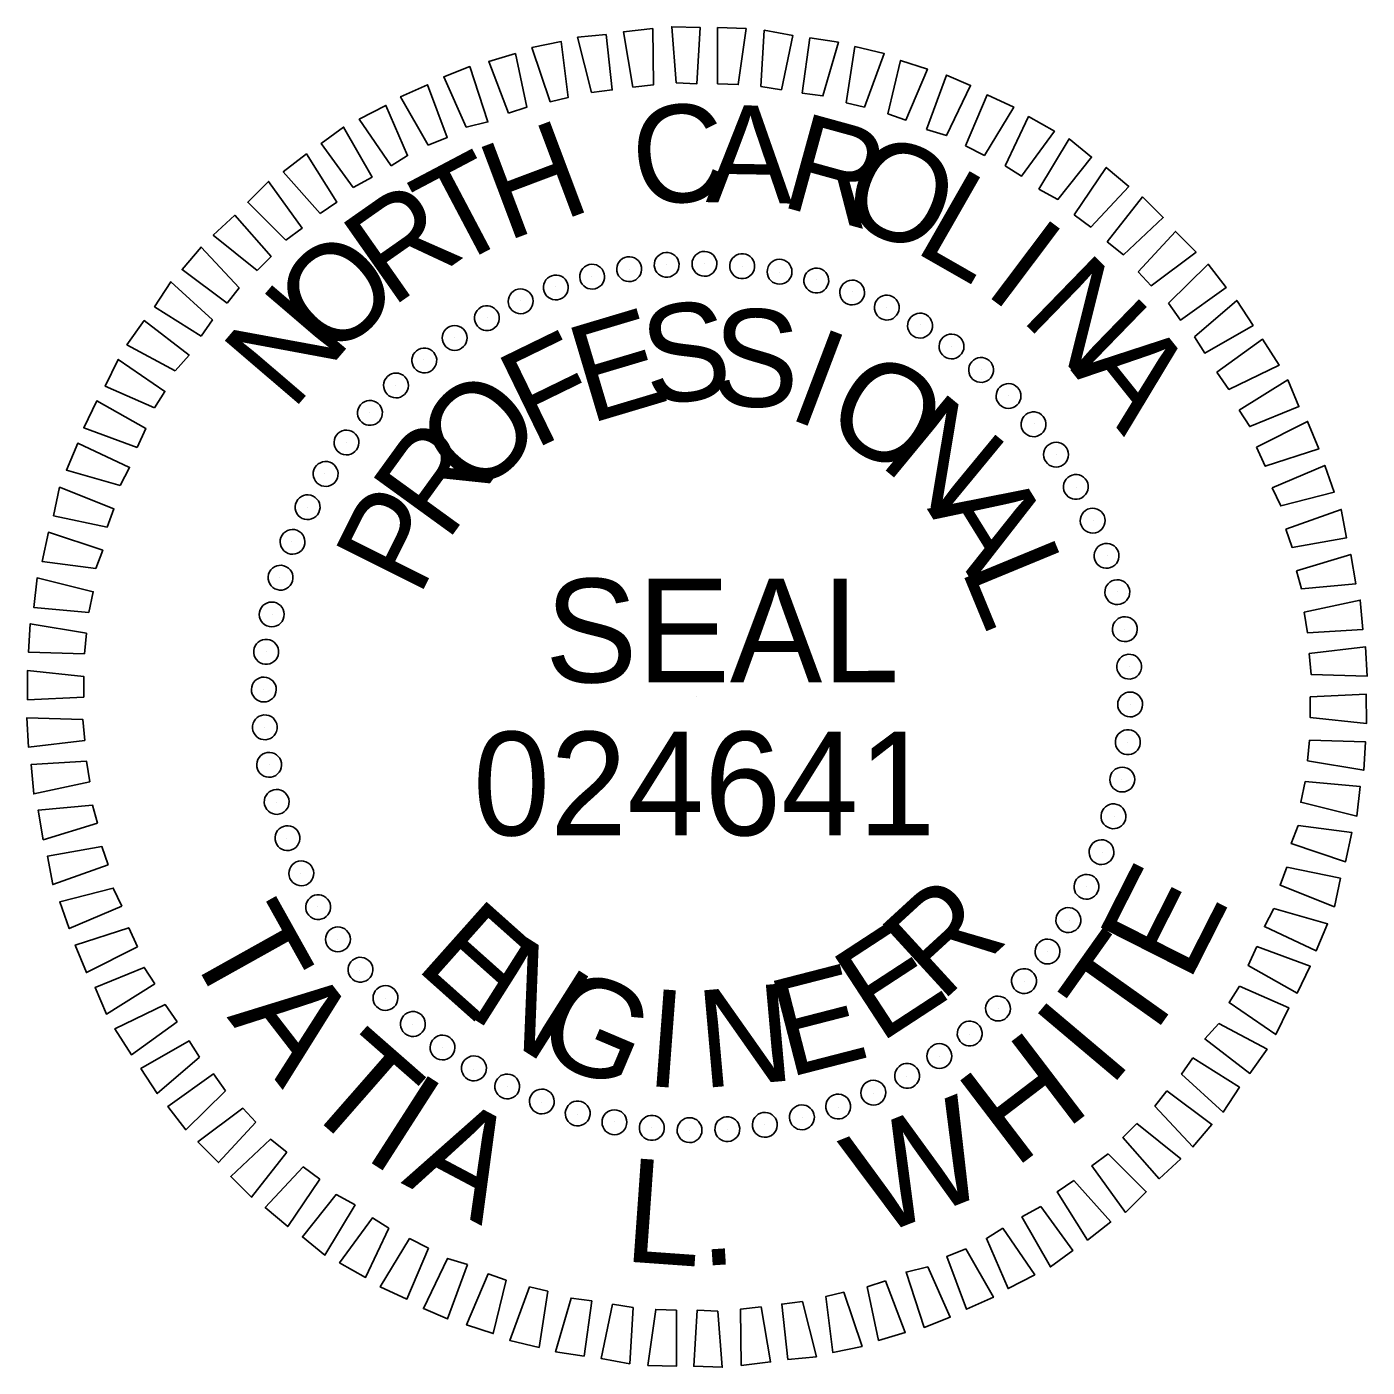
# Model space of a CAD drawing. Extents: x 573468 to 580768, y -57414 to -51768.
# Drawn here: x 580590.4 to 580668, y -54257.1 to -54179.5 of the extents above; entities that cross this region are included whole.
import ezdxf

# ---------------------------------------------------------------- set-up
doc = ezdxf.new("R2010")
doc.units = 0
doc.layers.add('Sheet Professional Seal CELL', color=7, linetype='Continuous')

msp = doc.modelspace()

# ---------------------------------------------------------------- linework, layer by layer
at = {"layer": 'Sheet Professional Seal CELL'}
for p, q in [((580625.308, -54193.527), (580625.308, -54193.527)), ((580627.458, -54193.227), (580627.458, -54193.227)), ((580629.658, -54193.176), (580629.658, -54193.176)), ((580631.858, -54193.325), (580631.858, -54193.325)), ((580634.008, -54193.675), (580634.008, -54193.675)), ((580621.008, -54194.528), (580621.008, -54194.528)), ((580623.108, -54193.928), (580623.108, -54193.928)), ((580636.108, -54194.124), (580636.108, -54194.124)), ((580619.008, -54195.329), (580619.008, -54195.329)), ((580638.208, -54194.824), (580638.208, -54194.824)), ((580640.208, -54195.723), (580640.208, -54195.723)), ((580617.059, -54196.329), (580617.059, -54196.329)), ((580642.159, -54196.723), (580642.159, -54196.723)), ((580615.159, -54197.48), (580615.159, -54197.48)), ((580643.959, -54197.972), (580643.959, -54197.972)), ((580613.409, -54198.73), (580613.409, -54198.73)), ((580645.709, -54199.322), (580645.709, -54199.322)), ((580611.76, -54200.23), (580611.76, -54200.23)), ((580647.26, -54200.822), (580647.26, -54200.822)), ((580610.26, -54201.781), (580610.26, -54201.781)), ((580648.76, -54202.471), (580648.76, -54202.471)), ((580608.91, -54203.531), (580608.91, -54203.531)), ((580650.011, -54204.221), (580650.011, -54204.221)), ((580607.661, -54205.331), (580607.661, -54205.331)), ((580651.161, -54206.121), (580651.161, -54206.121)), ((580606.661, -54207.282), (580606.661, -54207.282)), ((580652.162, -54208.07), (580652.162, -54208.07)), ((580605.762, -54209.282), (580605.762, -54209.282)), ((580652.962, -54210.07), (580652.962, -54210.07)), ((580605.062, -54211.382), (580605.062, -54211.382)), ((580653.563, -54212.17), (580653.563, -54212.17)), ((580604.613, -54213.482), (580604.613, -54213.482)), ((580653.963, -54214.37), (580653.963, -54214.37)), ((580604.263, -54215.632), (580604.263, -54215.632)), ((580654.264, -54216.52), (580654.264, -54216.52)), ((580604.114, -54217.832), (580604.114, -54217.832)), ((580629.214, -54218.276), (580629.214, -54218.276)), ((580654.314, -54218.72), (580654.314, -54218.72)), ((580604.165, -54220.032), (580604.165, -54220.032)), ((580654.165, -54220.92), (580654.165, -54220.92)), ((580604.465, -54222.182), (580604.465, -54222.182)), ((580653.815, -54223.07), (580653.815, -54223.07)), ((580604.866, -54224.382), (580604.866, -54224.382)), ((580653.366, -54225.17), (580653.366, -54225.17)), ((580605.466, -54226.482), (580605.466, -54226.482)), ((580652.666, -54227.27), (580652.666, -54227.27)), ((580606.267, -54228.482), (580606.267, -54228.482)), ((580651.767, -54229.27), (580651.767, -54229.27)), ((580607.267, -54230.432), (580607.267, -54230.432)), ((580650.767, -54231.221), (580650.767, -54231.221)), ((580608.418, -54232.331), (580608.418, -54232.331)), ((580649.518, -54233.021), (580649.518, -54233.021)), ((580609.668, -54234.081), (580609.668, -54234.081)), ((580648.168, -54234.771), (580648.168, -54234.771)), ((580611.168, -54235.731), (580611.168, -54235.731)), ((580646.669, -54236.322), (580646.669, -54236.322)), ((580612.719, -54237.23), (580612.719, -54237.23)), ((580645.019, -54237.822), (580645.019, -54237.822)), ((580614.469, -54238.58), (580614.469, -54238.58)), ((580643.269, -54239.073), (580643.269, -54239.073)), ((580616.27, -54239.829), (580616.27, -54239.829)), ((580641.37, -54240.223), (580641.37, -54240.223)), ((580618.22, -54240.829), (580618.22, -54240.829)), ((580620.22, -54241.728), (580620.22, -54241.728)), ((580639.42, -54241.224), (580639.42, -54241.224)), ((580622.32, -54242.428), (580622.32, -54242.428)), ((580635.32, -54242.625), (580635.32, -54242.625)), ((580637.42, -54242.024), (580637.42, -54242.024)), ((580624.42, -54242.877), (580624.42, -54242.877)), ((580626.57, -54243.227), (580626.57, -54243.227)), ((580628.77, -54243.376), (580628.77, -54243.376)), ((580630.97, -54243.326), (580630.97, -54243.326)), ((580633.12, -54243.025), (580633.12, -54243.025))]:
    msp.add_line(p, q, dxfattribs=at)
for points in [[(580625.505, -54182.977), (580624.955, -54179.777), (580626.654, -54179.577), (580626.705, -54182.827)], [(580628.005, -54182.726), (580627.754, -54179.476), (580629.404, -54179.526), (580629.205, -54182.776)], [(580630.405, -54182.776), (580630.404, -54179.526), (580632.054, -54179.575), (580631.605, -54182.825)], [(580632.905, -54182.925), (580633.104, -54179.675), (580634.755, -54179.975), (580634.105, -54183.125)], [(580620.706, -54183.828), (580619.655, -54180.678), (580621.355, -54180.328), (580621.755, -54183.578)], [(580623.105, -54183.278), (580622.305, -54180.078), (580623.955, -54179.927), (580624.305, -54183.127)], [(580635.305, -54183.325), (580635.755, -54180.124), (580637.405, -54180.374), (580636.505, -54183.474)], [(580637.856, -54183.874), (580638.355, -54180.624), (580640.055, -54181.023), (580638.906, -54184.124)], [(580618.306, -54184.479), (580617.155, -54181.479), (580618.705, -54181.029), (580619.356, -54184.129)], [(580640.256, -54184.523), (580641.005, -54181.423), (580642.555, -54181.923), (580641.306, -54184.873)], [(580615.856, -54185.279), (580614.555, -54182.38), (580616.055, -54181.779), (580617.106, -54184.979)], [(580613.656, -54186.33), (580612.055, -54183.53), (580613.605, -54182.83), (580614.756, -54185.88)], [(580642.506, -54185.423), (580643.655, -54182.272), (580645.055, -54182.872), (580643.656, -54185.772)], [(580644.756, -54186.372), (580646.005, -54183.422), (580647.556, -54184.122), (580645.856, -54186.922)], [(580611.506, -54187.531), (580609.656, -54184.831), (580611.206, -54184.031), (580612.456, -54186.93)], [(580609.307, -54188.781), (580607.456, -54186.232), (580608.756, -54185.281), (580610.407, -54188.181)], [(580647.056, -54187.522), (580648.406, -54184.671), (580649.906, -54185.521), (580648.007, -54188.121)], [(580649.007, -54188.871), (580650.756, -54185.971), (580652.056, -54187.02), (580650.107, -54189.471)], [(580607.407, -54190.282), (580605.257, -54187.882), (580606.606, -54186.832), (580608.357, -54189.631)], [(580651.057, -54190.371), (580652.906, -54187.62), (580654.207, -54188.72), (580652.007, -54191.07)], [(580605.408, -54191.832), (580603.207, -54189.633), (580604.407, -54188.432), (580606.357, -54191.132)], [(580652.958, -54191.92), (580655.007, -54189.32), (580656.207, -54190.519), (580653.908, -54192.67)], [(580603.758, -54193.582), (580601.207, -54191.533), (580602.457, -54190.383), (580604.558, -54192.782)], [(580654.758, -54193.67), (580656.907, -54191.319), (580658.108, -54192.519), (580655.508, -54194.47)], [(580602.008, -54195.483), (580599.408, -54193.534), (580600.508, -54192.233), (580602.708, -54194.583)], [(580656.508, -54195.469), (580658.808, -54193.219), (580659.858, -54194.568), (580657.209, -54196.469)], [(580600.509, -54197.383), (580597.808, -54195.684), (580598.758, -54194.234), (580601.159, -54196.433)], [(580658.009, -54197.419), (580660.458, -54195.318), (580661.409, -54196.768), (580658.609, -54198.369)], [(580599.009, -54199.384), (580596.209, -54197.884), (580597.209, -54196.484), (580599.809, -54198.483)], [(580659.309, -54199.469), (580661.959, -54197.568), (580662.909, -54199.068), (580660.01, -54200.468)], [(580597.81, -54201.534), (580594.96, -54200.285), (580595.709, -54198.734), (580598.41, -54200.584)], [(580660.61, -54201.668), (580663.41, -54199.918), (580664.06, -54201.467), (580661.21, -54202.618)], [(580596.811, -54203.834), (580593.71, -54202.685), (580594.46, -54201.135), (580597.31, -54202.734)], [(580661.611, -54203.818), (580664.56, -54202.317), (580665.211, -54203.917), (580662.111, -54204.918)], [(580595.811, -54206.034), (580592.711, -54205.135), (580593.36, -54203.585), (580596.361, -54204.984)], [(580662.511, -54206.168), (580665.561, -54204.867), (580666.111, -54206.417), (580663.011, -54207.218)], [(580595.062, -54208.435), (580591.962, -54207.785), (580592.311, -54206.135), (580595.461, -54207.385)], [(580663.312, -54208.568), (580666.511, -54207.417), (580666.812, -54209.067), (580663.662, -54209.617)], [(580594.412, -54210.835), (580591.312, -54210.436), (580591.662, -54208.735), (580594.812, -54209.785)], [(580663.912, -54210.967), (580667.062, -54210.017), (580667.362, -54211.717), (580664.213, -54212.017)], [(580594.013, -54213.385), (580590.813, -54213.086), (580591.012, -54211.386), (580594.263, -54212.185)], [(580664.363, -54213.367), (580667.613, -54212.666), (580667.763, -54214.366), (580664.563, -54214.567)], [(580593.764, -54215.785), (580590.513, -54215.686), (580590.613, -54214.036), (580593.863, -54214.585)], [(580664.664, -54215.767), (580667.913, -54215.366), (580668.014, -54217.066), (580664.764, -54216.967)], [(580593.714, -54218.285), (580590.464, -54218.436), (580590.464, -54216.736), (580593.714, -54217.085)], [(580664.714, -54218.267), (580667.964, -54218.116), (580667.965, -54219.816), (580664.714, -54219.467)], [(580593.765, -54220.785), (580590.515, -54221.186), (580590.414, -54219.486), (580593.664, -54219.585)], [(580664.665, -54220.767), (580667.915, -54220.866), (580667.815, -54222.516), (580664.565, -54221.967)], [(580594.065, -54223.185), (580590.816, -54223.886), (580590.665, -54222.186), (580593.865, -54221.985)], [(580664.415, -54223.167), (580667.615, -54223.466), (580667.416, -54225.167), (580664.166, -54224.367)], [(580594.516, -54225.585), (580591.366, -54226.536), (580591.066, -54224.836), (580594.216, -54224.535)], [(580664.016, -54225.717), (580667.116, -54226.117), (580666.767, -54227.817), (580663.616, -54226.767)], [(580595.117, -54227.985), (580591.917, -54229.135), (580591.616, -54227.485), (580594.766, -54226.935)], [(580663.367, -54228.118), (580666.467, -54228.767), (580666.117, -54230.417), (580662.967, -54229.168)], [(580595.917, -54230.384), (580592.867, -54231.685), (580592.317, -54230.135), (580595.417, -54229.335)], [(580662.617, -54230.518), (580665.717, -54231.417), (580665.068, -54232.967), (580662.067, -54231.568)], [(580596.818, -54232.734), (580593.868, -54234.235), (580593.218, -54232.635), (580596.317, -54231.634)], [(580661.618, -54232.718), (580664.718, -54233.867), (580663.968, -54235.417), (580661.118, -54233.818)], [(580597.818, -54234.884), (580595.019, -54236.635), (580594.368, -54235.085), (580597.218, -54233.934)], [(580660.618, -54235.018), (580663.469, -54236.268), (580662.719, -54237.818), (580660.019, -54235.968)], [(580599.119, -54237.084), (580596.469, -54238.984), (580595.519, -54237.485), (580598.419, -54236.084)], [(580659.419, -54237.169), (580662.219, -54238.668), (580661.22, -54240.068), (580658.619, -54238.069)], [(580600.419, -54239.133), (580597.97, -54241.234), (580597.02, -54239.784), (580599.819, -54238.183)], [(580657.919, -54239.169), (580660.62, -54240.868), (580659.67, -54242.318), (580657.27, -54240.119)], [(580601.92, -54241.083), (580599.62, -54243.333), (580598.57, -54241.984), (580601.22, -54240.083)], [(580656.42, -54241.069), (580659.02, -54243.019), (580657.921, -54244.319), (580655.72, -54241.969)], [(580603.67, -54242.882), (580601.521, -54245.233), (580600.321, -54244.033), (580602.92, -54242.083)], [(580654.67, -54242.97), (580657.221, -54245.019), (580655.971, -54246.169), (580653.871, -54243.77)], [(580605.471, -54244.632), (580603.421, -54247.233), (580602.221, -54246.033), (580604.521, -54243.882)], [(580653.021, -54244.72), (580655.221, -54246.92), (580654.022, -54248.12), (580652.071, -54245.42)], [(580607.371, -54246.182), (580605.522, -54248.932), (580604.222, -54247.832), (580606.421, -54245.482)], [(580651.021, -54246.271), (580653.172, -54248.67), (580651.822, -54249.72), (580650.071, -54246.921)], [(580609.421, -54247.681), (580607.672, -54250.581), (580606.372, -54249.532), (580608.321, -54247.081)], [(580649.122, -54247.771), (580650.972, -54250.321), (580649.672, -54251.271), (580648.022, -54248.371)], [(580611.372, -54249.031), (580610.023, -54251.881), (580608.522, -54251.031), (580610.422, -54248.431)], [(580613.672, -54250.18), (580612.423, -54253.13), (580610.873, -54252.431), (580612.572, -54249.63)], [(580646.922, -54249.022), (580648.772, -54251.721), (580647.223, -54252.522), (580645.972, -54249.622)], [(580644.772, -54250.222), (580646.373, -54253.022), (580644.823, -54253.722), (580643.672, -54250.672)], [(580615.922, -54251.129), (580614.773, -54254.28), (580613.373, -54253.68), (580614.772, -54250.78)], [(580642.572, -54251.273), (580643.873, -54254.172), (580642.373, -54254.773), (580641.322, -54251.573)], [(580618.173, -54252.029), (580617.423, -54255.129), (580615.873, -54254.629), (580617.122, -54251.679)], [(580620.573, -54252.678), (580620.074, -54255.928), (580618.373, -54255.529), (580619.523, -54252.429)], [(580637.723, -54252.724), (580638.774, -54255.874), (580637.074, -54256.224), (580636.673, -54252.974)], [(580640.123, -54252.073), (580641.273, -54255.073), (580639.723, -54255.523), (580639.073, -54252.424)], [(580623.123, -54253.228), (580622.674, -54256.428), (580621.024, -54256.178), (580621.923, -54253.078)], [(580625.523, -54253.627), (580625.324, -54256.877), (580623.674, -54256.577), (580624.323, -54253.427)], [(580632.923, -54253.575), (580633.474, -54256.775), (580631.774, -54256.975), (580631.723, -54253.725)], [(580635.323, -54253.275), (580636.124, -54256.474), (580634.474, -54256.625), (580634.123, -54253.425)], [(580628.023, -54253.776), (580628.024, -54257.026), (580626.374, -54256.977), (580626.823, -54253.727)], [(580630.423, -54253.826), (580630.674, -54257.076), (580629.024, -54257.026), (580629.223, -54253.776)]]:
    msp.add_lwpolyline(points, close=True, dxfattribs=at)
for centre, major_axis in [((580625.285, -54193.506), (-0.113, 0.711)), ((580627.458, -54193.258), (-0.05, 0.718)), ((580629.646, -54193.2), (0.012, 0.72)), ((580631.829, -54193.333), (0.075, 0.716)), ((580633.993, -54193.656), (0.137, 0.707)), ((580621.043, -54194.565), (-0.235, 0.681)), ((580623.141, -54193.943), (-0.174, 0.699)), ((580636.121, -54194.166), (0.198, 0.692)), ((580619.007, -54195.367), (-0.293, 0.658)), ((580638.196, -54194.86), (0.258, 0.672)), ((580640.203, -54195.732), (0.315, 0.647)), ((580617.05, -54196.344), (-0.349, 0.63)), ((580642.126, -54196.775), (0.371, 0.617)), ((580615.184, -54197.487), (-0.403, 0.597)), ((580643.951, -54197.982), (0.423, 0.583)), ((580613.426, -54198.789), (-0.453, 0.559)), ((580645.663, -54199.344), (0.472, 0.544)), ((580611.788, -54200.239), (-0.5, 0.518)), ((580647.251, -54200.85), (0.518, 0.5)), ((580610.282, -54201.827), (-0.544, 0.472)), ((580648.701, -54202.488), (0.559, 0.453)), ((580608.92, -54203.54), (-0.583, 0.423)), ((580650.003, -54204.246), (0.597, 0.403)), ((580607.713, -54205.364), (-0.617, 0.371)), ((580651.147, -54206.112), (0.63, 0.349)), ((580606.67, -54207.287), (-0.647, 0.315)), ((580652.123, -54208.069), (0.658, 0.293)), ((580605.798, -54209.294), (-0.672, 0.258)), ((580652.926, -54210.105), (0.681, 0.235)), ((580605.104, -54211.369), (-0.692, 0.198)), ((580653.548, -54212.203), (0.699, 0.174)), ((580604.594, -54213.497), (-0.707, 0.137)), ((580653.984, -54214.347), (0.711, 0.113)), ((580604.271, -54215.661), (-0.716, 0.075)), ((580654.233, -54216.52), (0.718, 0.05)), ((580604.138, -54217.845), (-0.72, 0.012)), ((580654.29, -54218.708), (0.72, -0.012)), ((580604.196, -54220.032), (-0.718, -0.05)), ((580654.157, -54220.891), (0.716, -0.075)), ((580604.444, -54222.206), (-0.711, -0.113)), ((580653.835, -54223.055), (0.707, -0.137)), ((580604.881, -54224.35), (-0.699, -0.174)), ((580653.324, -54225.183), (0.692, -0.198)), ((580605.503, -54226.447), (-0.681, -0.235)), ((580652.631, -54227.258), (0.672, -0.258)), ((580606.305, -54228.483), (-0.658, -0.293)), ((580651.759, -54229.265), (0.647, -0.315)), ((580607.282, -54230.441), (-0.63, -0.349)), ((580650.715, -54231.188), (0.617, -0.371)), ((580608.425, -54232.306), (-0.597, -0.403)), ((580649.508, -54233.013), (0.583, -0.423)), ((580609.727, -54234.064), (-0.559, -0.453)), ((580648.146, -54234.725), (0.544, -0.472)), ((580611.177, -54235.703), (-0.518, -0.5)), ((580646.641, -54236.313), (0.5, -0.518)), ((580612.765, -54237.208), (-0.472, -0.544)), ((580645.002, -54237.763), (0.453, -0.559)), ((580614.478, -54238.57), (-0.423, -0.583)), ((580643.244, -54239.065), (0.403, -0.597)), ((580616.302, -54239.777), (-0.371, -0.617)), ((580641.379, -54240.209), (0.349, -0.63)), ((580618.225, -54240.821), (-0.315, -0.647)), ((580639.421, -54241.185), (0.293, -0.658)), ((580620.232, -54241.693), (-0.258, -0.672)), ((580637.385, -54241.988), (0.235, -0.681)), ((580622.307, -54242.386), (-0.198, -0.692)), ((580635.288, -54242.61), (0.174, -0.699)), ((580624.435, -54242.896), (-0.137, -0.707)), ((580626.599, -54243.219), (-0.075, -0.716)), ((580628.783, -54243.352), (-0.012, -0.72)), ((580630.97, -54243.295), (0.05, -0.718)), ((580633.144, -54243.046), (0.113, -0.711))]:
    msp.add_ellipse(centre, major_axis=major_axis, ratio=0.999708, dxfattribs=at)

# ---------------------------------------------------------------- texts
for s, height, rotation, p in [('C', 5.638, 6.23419, (580625.757, -54189.927)), ('A', 5.638, 359.03464, (580629.707, -54189.626)), ('R', 5.638, 344.63542, (580633.907, -54189.825)), ('H', 5.638, 20.6338, (580618.158, -54191.929)), ('O', 5.638, 337.43548, (580637.257, -54190.574)), ('T', 5.638, 27.83409, (580614.908, -54193.58)), ('L', 5.638, 330.23519, (580641.658, -54192.423)), ('R', 5.639, 35.03482, (580611.509, -54195.781)), ('I', 5.638, 323.03446, (580645.708, -54194.822)), ('O', 5.638, 42.23606, (580608.059, -54198.881)), ('N', 5.639, 315.83323, (580647.859, -54196.371)), ('N', 5.639, 49.43782, (580605.76, -54201.782)), ('S', 5.638, 7.26993, (580626.41, -54201.427)), ('E', 5.638, 16.62539, (580622.96, -54202.478)), ('S', 5.638, 357.91472, (580630.01, -54201.376)), ('F', 5.638, 25.98135, (580619.761, -54203.978)), ('I', 5.638, 339.20392, (580634.31, -54202.075)), ('A', 5.639, 308.63147, (580650.809, -54199.321)), ('O', 5.638, 329.8478, (580636.31, -54202.774)), ('O', 5.639, 44.69556, (580616.461, -54206.929)), ('N', 5.638, 320.49093, (580639.661, -54204.773)), ('R', 5.639, 54.05397, (580614.712, -54209.38)), ('A', 5.639, 301.77459, (580642.511, -54207.373)), ('P', 5.639, 63.41321, (580613.113, -54212.58)), ('L', 5.639, 292.41517, (580644.462, -54210.822)), ('SEAL', 5.9982, 0.01432, (580620.415, -54217.43)), ('024641', 5.9982, 0.01432, (580616.245, -54226.288)), ('E', 5.998, 63.13321, (580657.651, -54234.924)), ('R', 5.639, 42.49573, (580643.319, -54236.023)), ('T', 5.998, 299.17946, (580599.522, -54232.566)), ('E', 5.638, 318.29121, (580612.818, -54233.93)), ('E', 5.638, 33.13841, (580639.769, -54238.373)), ('T', 5.998, 54.61139, (580654.87, -54238.954)), ('N', 5.638, 327.64827, (580615.819, -54236.629)), ('E', 5.638, 14.42608, (580634.47, -54240.325)), ('A', 5.998, 307.70128, (580601.968, -54236.808)), ('G', 5.638, 337.00456, (580619.619, -54238.878)), ('N', 5.638, 5.07071, (580629.52, -54240.926)), ('I', 5.638, 355.71552, (580626.17, -54240.777)), ('I', 5.998, 49.84692, (580653.064, -54241.014)), ('T', 5.998, 318.77965, (580606.036, -54241.698)), ('H', 5.998, 37.33533, (580647.571, -54245.64)), ('I', 5.998, 327.30147, (580609.763, -54244.874)), ('W', 5.998, 21.62807, (580639.478, -54249.588)), ('A', 5.998, 332.06594, (580612.04, -54246.398)), ('L', 5.998, 355.92704, (580624.883, -54250.942)), ('.', 5.998, 3.79035, (580629.393, -54251.227))]:
    msp.add_text(s, height=height, rotation=rotation, dxfattribs=at).set_placement(p)

doc.saveas('drawing.dxf')
